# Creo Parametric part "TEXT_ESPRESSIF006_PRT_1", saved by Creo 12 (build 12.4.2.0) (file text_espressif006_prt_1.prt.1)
Units: Custom; MM, KILOGRAM, SECS

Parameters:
  PTC_WM_ITERATION = "0"
  PTC_WM_VERSION = "-.0"
  PTC_WM_LIFECYCLE_STATE = "In Work"
  PTC_WM_LIFECYCLE = "MO_CADDocument"
  PTC_WM_CREATED_BY = "Maximilian Roepper (Z0017RMS: MO)"
  PTC_WM_CREATED_ON = "18-Sep-26 11:36:42 AM"
  PTC_WM_MODIFIED_BY = "Maximilian Roepper (Z0017RMS: MO)"
  PTC_WM_MODIFIED_ON = "18-Sep-26 11:36:46 AM"
  PDMLINKNUMBER = "PDM000071454862"
  PTC_WM_NAME = "text_espressif006_prt_1.prt"
  PTC_WM_NUMBER = "PDM000071454862"

Other parameters: WEIGHT, WEIGHT_FACTOR, WEIGHT_ADD, _MASS_TEMP, _DIFF_TEMP, MC_ERRORS, SUPPLIER

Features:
  1. coordinate system
  2. datum plane "PRT_YZ"
  3. datum plane "PRT_XY"
  4. datum plane "PRT_XZ"
  5. coordinate system
  6. datum axis
  7. datum axis
  8. datum axis
  9. coordinate system
  10. imported feature
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
Other named items: PRT, SIEMENS_MO, DRW_VIEW_ORG, PRT_X, PRT_Y, PRT_Z, CS0, ROUGH_GROB

Layers: 00_STD_CSYS-KSYS, 01_STD_PLANES-EBENEN, 02_STD_AXES-ACHSEN, 03_STD_CSYS-KSYS, 24_IMPORT_FEAT-IMPORT_KE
